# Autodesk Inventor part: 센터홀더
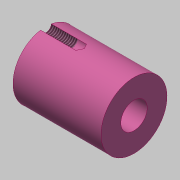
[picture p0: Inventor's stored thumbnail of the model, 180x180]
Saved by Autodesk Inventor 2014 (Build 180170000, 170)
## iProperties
Created: 2019-10
Part Number: 센터홀더
Material: 강철, 연강
Document SubType Name: Modeling
Designer: mduedu
Density: 1 g/cm^3
Appearance: 분홍색
Author: mduedu
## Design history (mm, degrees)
sketch "스케치1"
  geometry: L1 (0, 0)-(20, 0); L2 (12, -3)-(20, -3); L3 (20, -3)-(20, -7.5); L4 (20, -7.5)-(0, -7.5); L5 (0, -7.5)-(0, -4.127); L6 (0, -4.127)-(12, -3.751); L7 (12, -3.751)-(12, -3)
  constraints: 14 end point, 2 horizontal, 2 parallel, 2 perpendicular, 2 vertical alignment
  dimensions: "d0" = 20 distance of L1.start L1.end; "d1" = 6 diameter of L2 L1; "d2" = 12 distance between parallel lines of L5 L7; "d3" = 7.502 diameter of L6.end L1; "d4" = 8.254 diameter of L5.end L1; "d5" = 15 diameter of L4 L1
revolve "회전1" sketch "스케치1" stored, may be unused: angle "d6" = 90 deg
sketch "스케치2"
  geometry: 3 further points
  constraints: 2 vertical alignment, 1 other
hole "구멍1" sketch "스케치2" at (0, 7.5) diameter "d7" = 2.459; stored, may be unused: countersink angle "d11" = 90 deg, drill point angle "d13" = 118 deg; dims "d8" = 6, "d9" = 4, "d10" = 2, "d12" = 8
node "솔리드1"
